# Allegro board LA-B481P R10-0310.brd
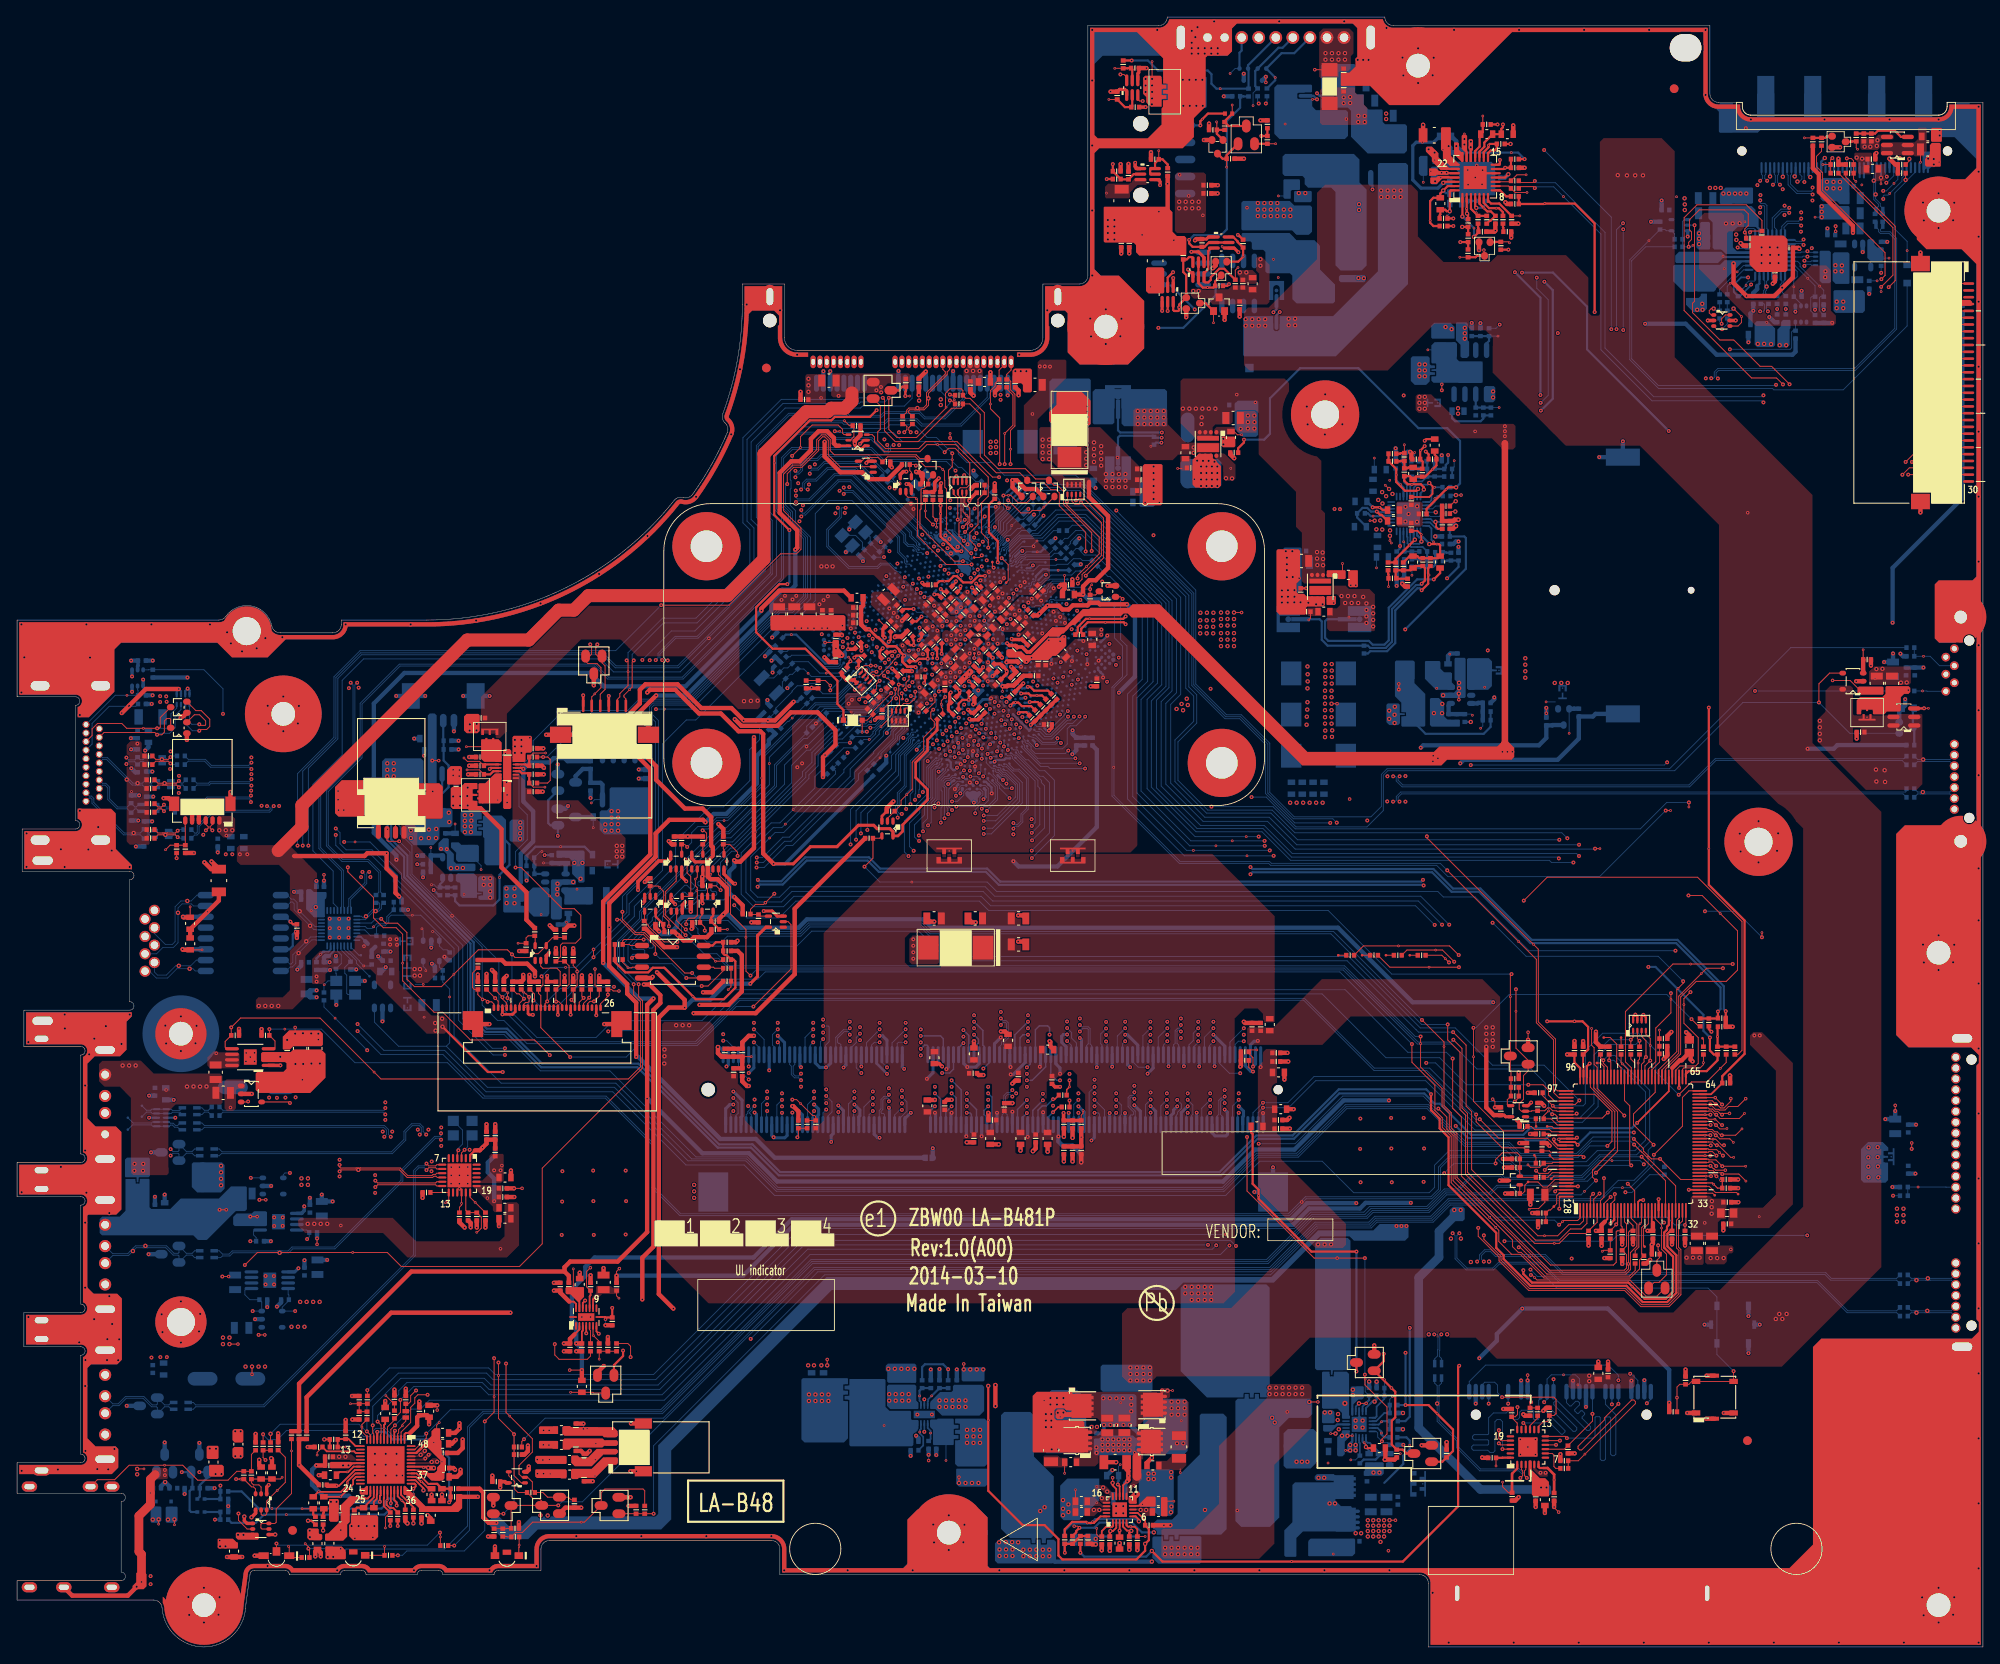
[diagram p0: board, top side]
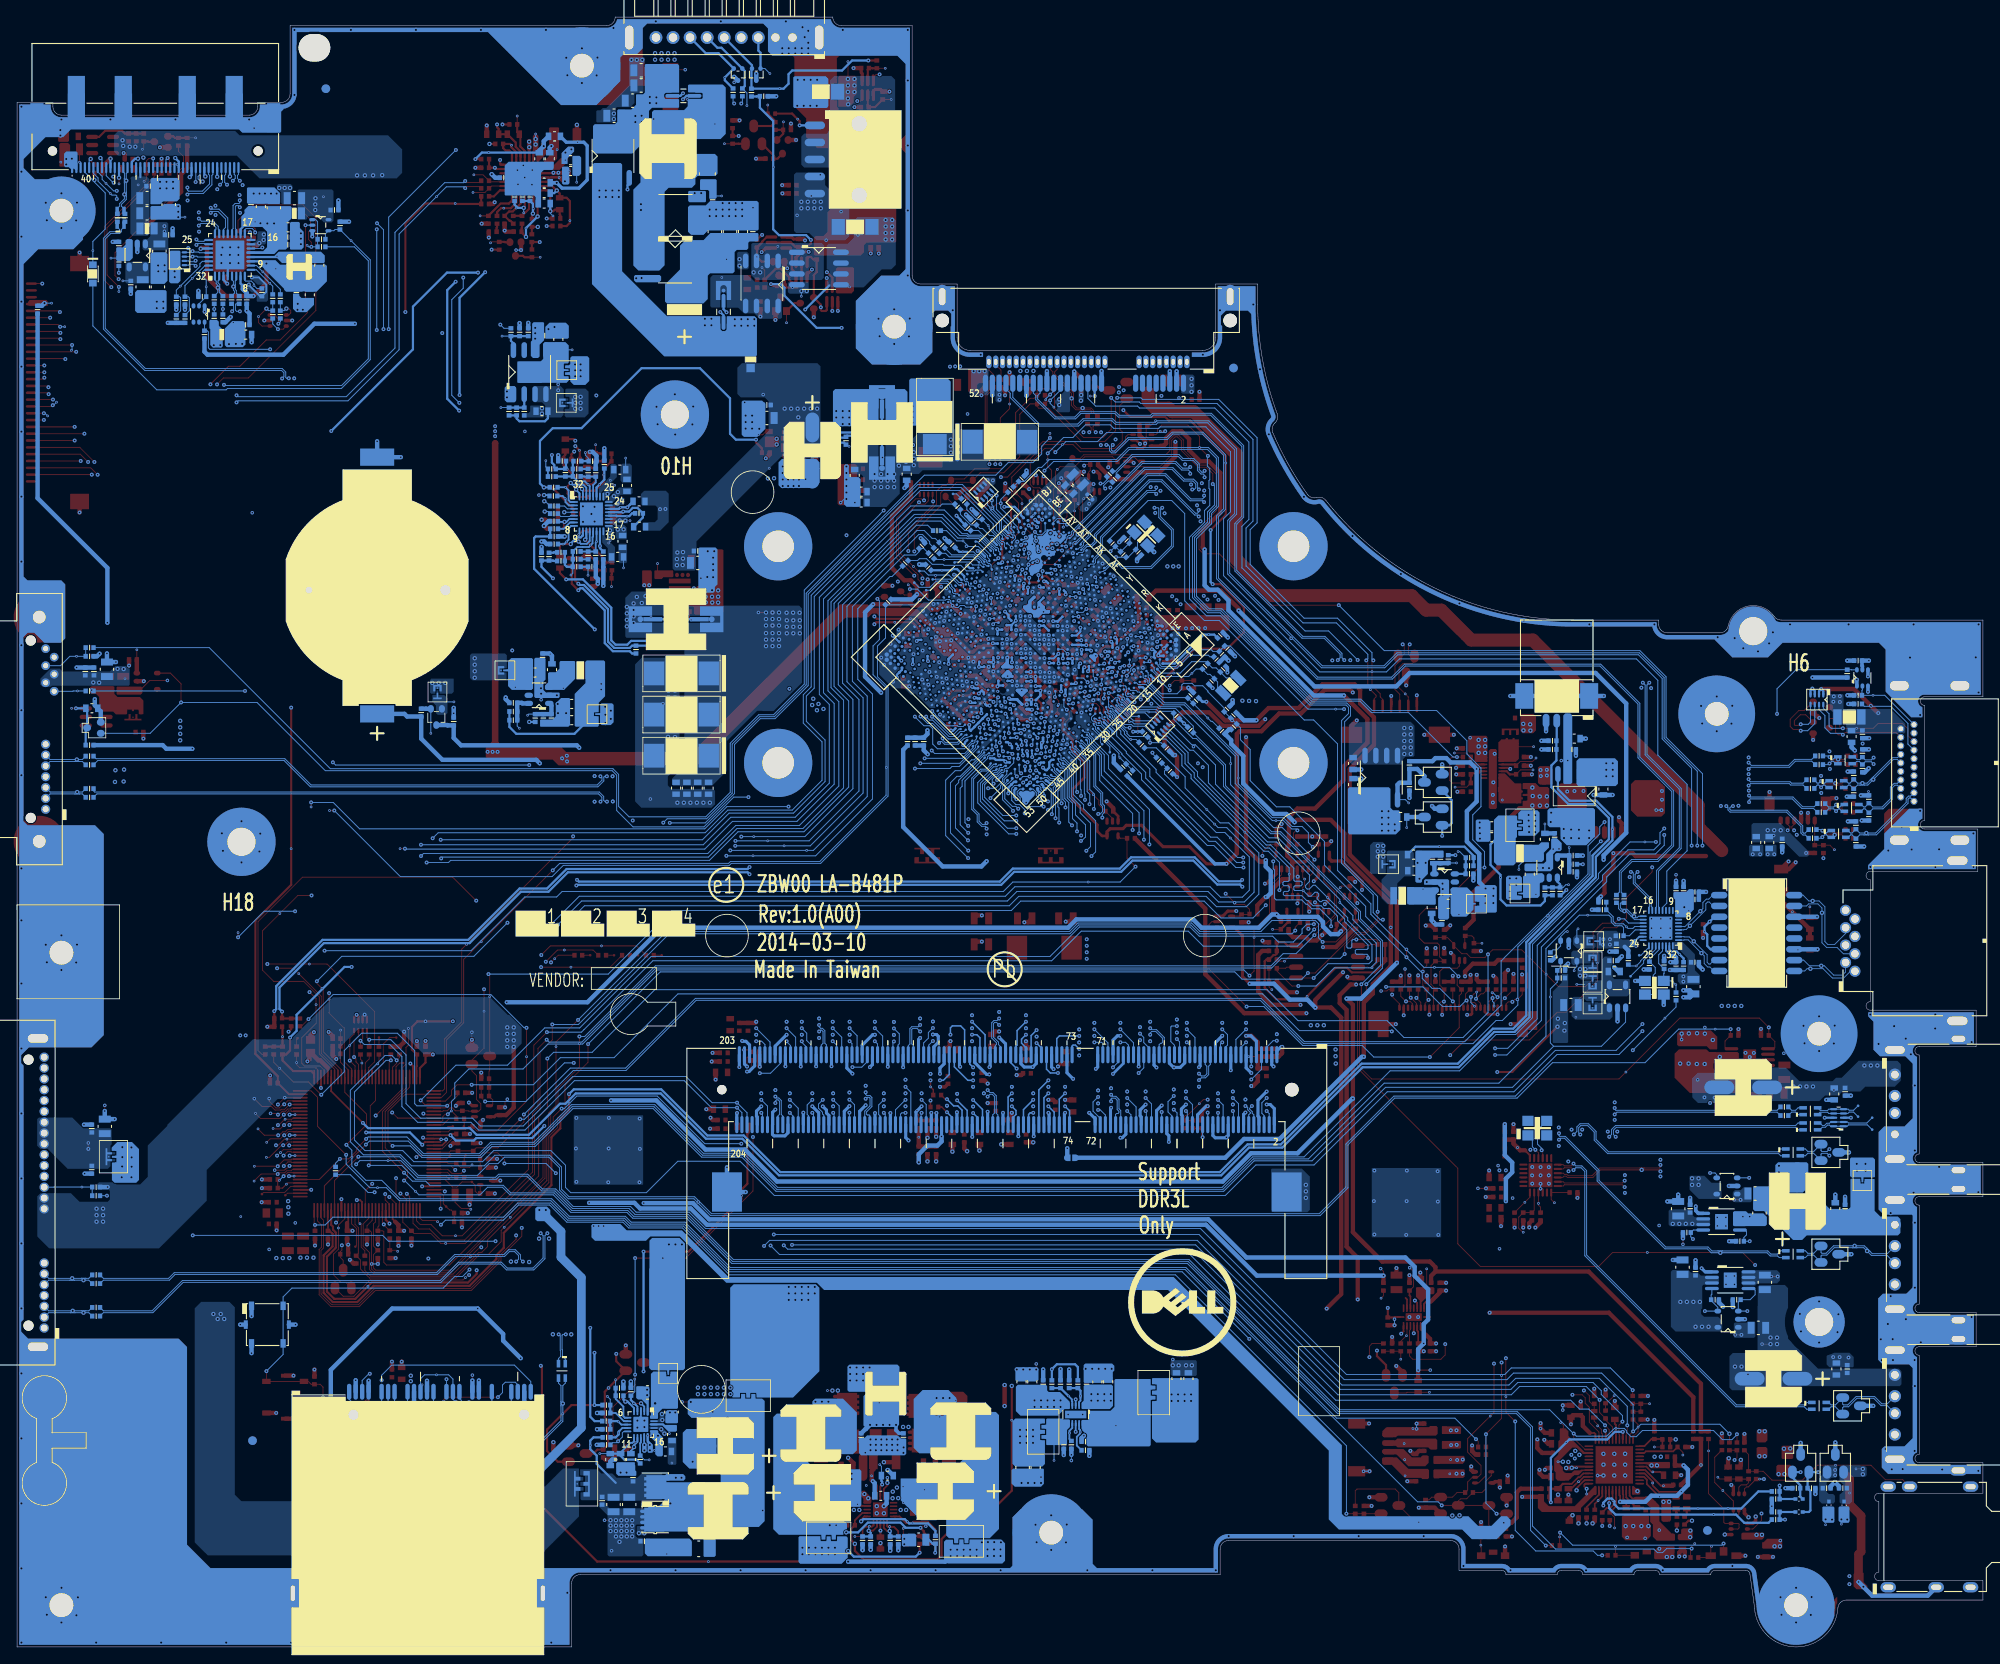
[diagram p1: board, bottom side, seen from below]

Outline 230.4 x 191.1 mm; copper layers: TOP, VCC, IN1, IN2, GND, BOTTOM. Coordinates in mm from the lower left corner of the outline.
Outline path: 0,120.4 0,111.4 6.85,111.4 arc(7.35,110.9) 6.85,110.4 6.85,96.9 arc(7.35,96.4) 6.85,95.9 0.6,95.9 0.6,90.94 13.2,90.94 arc(13.7,90.44) 13.2,89.94 13.2,75.66 arc(13.7,75.16) 13.2,74.66 0.8,74.66 0.8,70.4 7.47,70.4 arc(7.97,69.9) 7.47,69.4 7.47,57.8 arc(7.97,57.3) 7.47,56.8 0,56.8 0,52.8 7.47,52.8 arc(7.97,52.3) 7.47,51.8 7.47,40.2 arc(7.97,39.7) 7.47,39.2 0.8,39.2 0.8,35.2 7.47,35.2 arc(7.97,34.7) 7.47,34.2 7.47,22.6 arc(7.97,22.1) 7.47,21.6 0,21.6 0,18.02 12.2,18.02 arc(12.7,17.53) 12.2,17.02 12.2,8.78 arc(12.7,8.28) 12.2,7.78 0,7.78 0,5.5 16,5.5 arc(16.68,5.23) 17,4.57 arc(21.88,0) 26.77,4.55 arc(26.8,4.88) 26.84,5.22 27.3,8.48 arc(27.45,8.83) 27.8,8.98 31.4,8.98 arc(31.75,8.83) 31.9,8.48 37.9,8.48 arc(38.05,8.83) 38.4,8.98 40.4,8.98 arc(40.75,8.83) 40.9,8.48 46.9,8.48 arc(47.05,8.83) 47.4,8.98 49.4,8.98 arc(49.75,8.83) 49.9,8.48 55.9,8.48 arc(56.05,8.83) 56.4,8.98 61.4,8.98 61.4,11.48 arc(61.69,12.19) 62.4,12.48 88.4,12.48 arc(89.11,12.19) 89.4,11.48 89.4,8.48 164.4,8.48 arc(165.11,8.19) 165.4,7.48 165.4,0 230.4,0 230.4,181.1 226.2,181.1 226.2,180.6 arc(225.91,179.89) 225.2,179.6 203.2,179.6 arc(202.49,179.89) 202.2,180.6 202.2,181.1 199.4,181.1 arc(198.69,181.39) 198.4,182.1 198.4,190.1 161.3,190.1 arc(160.59,190.39) 160.3,191.1 134.8,191.1 arc(134.51,190.39) 133.8,190.1 125.5,190.1 125.5,160.8 arc(125.21,160.09) 124.5,159.8 120.23,159.8 120.23,153.52 arc(119.79,152.46) 118.73,152.02 91.43,152.02 arc(90.37,152.46) 89.93,153.52 89.93,159.8 85,159.8 85,157.4 arc(84.42,150.9) 82.71,144.59 arc(82.68,144.01) 82.98,143.51 arc(83.29,142.98) 83.23,142.37 arc(81.4,138.65) 79.17,135.14 arc(78.68,134.78) 78.07,134.77 arc(77.49,134.76) 77.01,134.43 arc(64.11,124.09) 48,120.4 38,120.4 38,119.9 arc(37.71,119.19) 37,118.9 30.84,118.9 arc(30.21,119.13) 29.86,119.7 arc(27.53,122.04) 24.46,120.83 arc(24.11,120.51) 23.65,120.4 0,120.4

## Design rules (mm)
net group CARD-READER: nets MS_INS# SD_CD#
net group CLK_PCIE_LAN: nets CLK_PCIE_LAN CLK_PCIE_LAN#
net group CLK_PCIE_WLAN: nets CLK_PCIE_WLAN CLK_PCIE_WLAN#
net group CPU_EDP_0_C: nets CPU_EDP_N0_C CPU_EDP_P0_C
net group CPU_EDP_AUX_C: nets CPU_EDP_AUX#_C CPU_EDP_AUX_C
net group DDI0_RCOMP: nets DDI0_RCOMPN DDI0_RCOMPP
net group DDR_A_ODT0: nets DDR_A_ODT0 M_ODT0
net group DDR_A_ODT2: nets DDR_A_ODT2 M_ODT1
net group DIFFPAIR1: nets CSCL CSDA
net group DIFFPAIR2: nets CSIN CSIP
net group DIFFPAIR3: nets DBG_UART_RXD DBG_UART_TXD
net group EDP_CPU_AUX: nets EDP_CPU_AUX EDP_CPU_AUX#
net group EDP_CPU_LANE_0: nets EDP_CPU_LANE_N0 EDP_CPU_LANE_P0
net group HDMI_CLK: nets HDMI_CLK+ HDMI_CLK-
net group HDMI_TX0: nets HDMI_TX0+ HDMI_TX0-
net group HDMI_TX1: nets HDMI_TX1+ HDMI_TX1-
net group HDMI_TX2: nets HDMI_TX2+ HDMI_TX2-
net group ICLK_USB_TERM: nets ICLK_USB_TERMN ICLK_USB_TERMP
net group LVDS_A0: nets LVDS_A0+ LVDS_A0-
net group LVDS_A1: nets LVDS_A1+ LVDS_A1-
net group LVDS_A2: nets LVDS_A2+ LVDS_A2-
net group LVDS_ACLK: nets LVDS_ACLK+ LVDS_ACLK-
net group MDI0: nets MDI0+ MDI0-
net group MDI1: nets MDI1+ MDI1-
net group MDO0: nets MDO0+ MDO0-
net group MDO1: nets MDO1+ MDO1-
net group MS_CLK_SD_WP: nets MS_CLK_SD_WP MS_CLK_SD_WP_R
net group MS_D2_SD_CLK: nets MS_D2_SD_CLK MS_D2_SD_CLK_R
net group PCH_USB3_RX0_: nets PCH_USB3_RX0_N PCH_USB3_RX0_P
net group PCH_USB3_TX0_: nets PCH_USB3_TX0_N PCH_USB3_TX0_P
net group PCH_USB3_TX0__C: nets PCH_USB3_TX0_N_C PCH_USB3_TX0_P_C
net group PCIE_PRX_C_DTX_0: nets PCIE_PRX_C_DTX_N0 PCIE_PRX_C_DTX_P0
net group PCIE_PRX_DTX_1: nets PCIE_PRX_DTX_N1 PCIE_PRX_DTX_P1
net group PCIE_PTX_C_DRX_0: nets PCIE_PTX_C_DRX_N0 PCIE_PTX_C_DRX_P0
net group PCIE_PTX_C_DRX_1: nets PCIE_PTX_C_DRX_N1 PCIE_PTX_C_DRX_P1
net group PCIE_PTX_DRX_0: nets PCIE_PTX_DRX_N0 PCIE_PTX_DRX_P0
net group PCIE_PTX_DRX_1: nets PCIE_PTX_DRX_N1 PCIE_PTX_DRX_P1
net group PCIE_RCOMP: nets PCIE_RCOMPN PCIE_RCOMPP
net group SATA_PRX_DTX_0: nets SATA_PRX_DTX_N0 SATA_PRX_DTX_P0
net group SATA_PRX_DTX_0_C: nets SATA_PRX_DTX_N0_C SATA_PRX_DTX_P0_C
net group SATA_PRX_DTX_1: nets SATA_PRX_DTX_N1 SATA_PRX_DTX_P1
net group SATA_PRX_DTX_1_C: nets SATA_PRX_DTX_N1_C SATA_PRX_DTX_P1_C
net group SATA_PTX_DRX_0: nets SATA_PTX_DRX_N0 SATA_PTX_DRX_P0
net group SATA_PTX_DRX_0_C: nets SATA_PTX_DRX_N0_C SATA_PTX_DRX_P0_C
net group SATA_PTX_DRX_1: nets SATA_PTX_DRX_N1 SATA_PTX_DRX_P1
net group SATA_PTX_DRX_1_C: nets SATA_PTX_DRX_N1_C SATA_PTX_DRX_P1_C
net group SATA_RCOMP: nets SATA_RCOMPN SATA_RCOMPP
net group TMDS_L_TX0: nets TMDS_L_TX0N TMDS_L_TX0P
net group TMDS_L_TX1: nets TMDS_L_TX1N TMDS_L_TX1P
net group TMDS_L_TX2: nets TMDS_L_TX2N TMDS_L_TX2P
net group TMDS_L_TXC: nets TMDS_L_TXCN TMDS_L_TXCP
net group TMDS_TX0: nets TMDS_TX0N TMDS_TX0P
net group TMDS_TX1: nets TMDS_TX1N TMDS_TX1P
net group TMDS_TX2: nets TMDS_TX2N TMDS_TX2P
net group TMDS_TXC: nets TMDS_TXCN TMDS_TXCP
net group USB3R2_JUSB1_R: nets USB3RN2_JUSB1_R USB3RP2_JUSB1_R
net group USB3T2_JUSB1_R: nets USB3TN2_JUSB1_R USB3TP2_JUSB1_R
net group USB20_0: nets USB20_N0 USB20_P0
net group USB20_1: nets USB20_N1 USB20_P1
net group USB20_2: nets USB20_N2 USB20_P2
net group USB20_CAM_7_R: nets USB20_CAM_N7_R USB20_CAM_P7_R
net group USB20_CPU_3: nets USB20_CPU_N3 USB20_CPU_P3
net group USB20_CR_3_R: nets USB20_CR_N3_R USB20_CR_P3_R
net group USB20_HUB_1: nets USB20_HUB_N1 USB20_HUB_P1
net group USB20_HUB_2: nets USB20_HUB_N2 USB20_HUB_P2
net group USB20_HUB_3: nets USB20_HUB_N3 USB20_HUB_P3
net group USB20_JUSB1_0_R: nets USB20_JUSB1_N0_R USB20_JUSB1_P0_R
net group USB20_JUSB2_1_R: nets USB20_JUSB2_N1_R USB20_JUSB2_P1_R
net group USB20_JUSB3_3_R: nets USB20_JUSB3_N3_R USB20_JUSB3_P3_R
net group VCORE_VSNS: nets VCORE_GSNS VCORE_VSNS
net group VSUM: nets N100765116 VSUM-
net group VSUMG: nets N100764996 VSUMG-
net group 10: nets AUD_HP_OUT_L_CN AUD_HP_OUT_R_CN HPOUT-L HPOUT-R LINE-IN-L LINE-IN-R MIC_IN
net group 15: nets CLK_SMB EC_SPI_CLK_R LAN_CLKREQ# MIC_CLK MIC_CLK_C PMC_SUSCLK SOC_I2C0_CLK
net group 20: nets DDR_RCOMP0 DDR_RCOMP1 DDR_RCOMP2 DDR_TERMN0 DDR_TERMN1 GPIO_RCOMP HDA_BIT_CLK HDA_BITCLK_AUDIO HDA_RCOMP HDA_RST# HDA_RST_AUDIO# HSIC_RCOMP HUB_XIN HUB_XOUT ICLK_ICOMP ICLK_RCOMP LPC_RCOMP USB3_REXT0 USB_RCOMP VGFX_VSNS VSUM+ VSUMG+ XTAL_25M_IN XTAL_25M_OUT XTLI XTLO
net group AUDIO-SPK: nets SPK_L1-_CONN SPK_L2+_CONN SPK_R1-_CONN SPK_R2+_CONN
net group HDA: nets HDA_SDIN0 HDA_SDOUT HDA_SDOUT_AUDIO HDA_SYNC HDA_SYNC_AUDIO
net group HDMI: nets CPU_DPB_CTRLCLK_R CPU_DPB_CTRLDAT_R HDMI_DDCCLK HDMI_DDCDATA
net group KB: nets KSI0 KSI1 KSI2 KSI3 KSI4 KSI5 KSI6 KSI7 KSO0 KSO1 KSO2 KSO3 KSO4 KSO5 KSO6 KSO7 KSO8 KSO9 KSO10 KSO11 KSO12 KSO13 KSO14 KSO15 KSO16
net group LPC: nets LPC_AD0 LPC_AD1 LPC_AD2 LPC_AD3 LPC_CLK_0 LPC_CLK_1 LPC_CLK_EC LPC_FRAME# SOC_SERIRQ
net group RTC: nets ILB_RTC_EXTPAD ILB_RTC_X1 ILB_RTC_X2 RTC_RST# RTC_TEST#
net group SMBUS: nets EC_RX EC_SMB_CK1 EC_SMB_CK2 EC_SMB_DA1 EC_SMB_DA2 EC_TX PCU_SMB_CLK PCU_SMB_DATA TP_CLK TP_DATA
net group SPI: nets SOC_SPI_CLK SOC_SPI_CS0# SOC_SPI_MISO SOC_SPI_MOSI SPI_CLK SPI_CS0# SPI_HOLD# SPI_MISO SPI_MOSI SPI_WP#
net group SVID: nets VR_SVID_ALERT# VR_SVID_CLK VR_SVID_CLK_R VR_SVID_DATA VR_SVID_DATA_R
net group XDP: nets XDP_H_PRDY# XDP_H_PREQ_BUF# XDP_H_TCK XDP_H_TDI XDP_H_TDO XDP_H_TMS XDP_H_TRST#
nets with their own width: min track width 0.254; nets +BIOS_SPI MIC_IN_R RING2 XTLI_R
nets with their own width: min track width 0.508; nets +0.675VSP +1.0VALW +1.0VALWP +1.0VS +1.0VS_R +1.05VS +1.5VS +1.05VS_SOC +1.05VSP +1.5VSP +1.8VALW +1.8VALWP +1.8VGS +1.8VS +1.8VS_OUT +1.8VSP_ON +1.35V +1.35V_SOC +1.35VP +1.35VS +1.35VS_OUT +3V_HUB +3V_WLAN +3VALW +3VALW_EC +3VALW_SOC +3VALWP +3VLP +3VS +3VS_CAM +3VS_LCDIN +3VS_OUT +3VS_RT +3VS_SOC +5VALW +5VALWP +5VS +5VS_TOUCH +AVCC33 +CHGRTC +CODEC_AVDD2 +DDR_SOC_VREF +DIMM1_VREF_CA +DIMM1_VREF_DQ +DVCC33 +EC_VCCA +INV_PWR_SRC +INV_PWR_SRC_R +MIC2-VREFO +RTCBATT +RTCBATT_R +RTCVCC +SOC_VCC +SOC_VNN +SW_LX +SWR_V12 +V18R +VDISPLAY_VCC GND
nets with their own width: min track width 0.762; nets +FAN_POWER INT-SPK-L+ INT-SPK-L- INT-SPK-R+ INT-SPK-R-
nets with their own width: min track width 1.016; nets +5V_HUB +5V_PVDD +5VA +LAN_VDD +VCC_3IN1
nets with their own width: min track width 1.524; nets +0.675VS +LAN_IO +LCDVDD +LCDVDD_CONN TL_ENVDD
nets with their own width: min track width 2.032; nets +5V_USB_PWR1 +5V_USB_PWR2 +5V_USB_PWR3
nets with their own width: min track width 4.572; nets +5VS_OUT

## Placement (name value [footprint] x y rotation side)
C182  0.1U_0402_16V7K  [C_0402]  77 95.02 270 top
C967  330P_0402_50V7K  [C_0402]  106.84 23.24 90 bottom
C976  330P_0402_50V7K  [C_0402]  104.73 23.06 0 bottom
C979  .1U_0402_16V7K  [C_0402]  108.11 31.27 270 bottom
C980  .1U_0402_16V7K  [C_0402]  107.09 30.35 90 bottom
C1034  1U_0402_6.3V6K  [C_0402]  95.94 118.68 270 top
C1035  1U_0402_6.3V6K  [C_0402]  95.94 115.48 90 top
C1036  1U_0402_6.3V6K  [C_0402]  106 117.49 315 top
C1037  1U_0402_6.3V6K  [C_0402]  105.25 116.22 225 top
C1038  0.47U_0402_6.3V6K  [C_0402]  110.08 111.4 225 top
C1039  0.01U_0402_16V7K  [C_0402]  104.33 119.11 315 top
C1040  1U_0402_6.3V6K  [C_0402]  112.06 112.64 45 top
C1041  1U_0402_6.3V6K  [C_0402]  113.88 116.39 135 top
C1042  1U_0402_6.3V6K  [C_0402]  115.01 116.5 135 top
C1043  1U_0402_6.3V6K  [C_0402]  109.43 122.98 315 top
C1044  1U_0402_6.3V6K  [C_0402]  106.65 119.4 225 top
C1045  1U_0402_6.3V6K  [C_0402]  103.86 114.44 225 top
C1046  1U_0402_6.3V6K  [C_0402]  116.56 121.8 135 top
C1047  1U_0402_6.3V6K  [C_0402]  115.92 121.16 135 top
C1048  1U_0402_6.3V6K  [C_0402]  95.41 121.56 270 top
C1049  1U_0402_6.3V6K  [C_0402]  94.39 121.56 270 top
C1050  1U_0402_6.3V6K  [C_0402]  113.62 123.59 315 top
C1051  1U_0402_6.3V6K  [C_0402]  117.82 118.11 45 top
C1052  1U_0402_6.3V6K  [C_0402]  110.81 123.13 315 top
C1053  1U_0402_6.3V6K  [C_0402]  118.45 117.48 45 top
C1054  1U_0402_6.3V6K  [C_0402]  112.77 110.16 315 top
C1055  1U_0402_6.3V6K  [C_0402]  112.13 109.52 315 top
C1056  22U_0805_6.3V6M  [C_0805]  92.87 121.96 270 top
C1057  22U_0805_6.3V6M  [C_0805]  91.09 121.96 270 top
C1058  1U_0402_6.3V6K  [C_0402]  117.19 117.24 225 top
C1059  22U_0805_6.3V6M  [C_0805]  89.31 121.96 270 top
C1060  1U_0402_6.3V6K  [C_0402]  101.31 115.96 45 top
C1061  1U_0402_6.3V6K  [C_0402]  115.52 114.98 225 top
C1062  1U_0402_6.3V6K  [C_0402]  107.08 117.7 315 top
C1063  .1U_0402_16V7K  [C_0402]  98.91 120.09 180 top
C1064  1U_0402_6.3V6K  [C_0402]  118.15 120.05 225 top
C1065  1U_0402_6.3V6K  [C_0402]  98.91 121.87 180 top
C1066  1U_0402_6.3V6K  [C_0402]  117.43 120.59 225 top
C1067  1U_0402_6.3V6K  [C_0402]  98.91 120.98 180 top
C1068  1U_0402_6.3V6K  [C_0402]  108.8 122.34 315 top
C1069  .1U_0402_16V7K  [C_0402]  114.26 124.48 315 top
C1070  0.01U_0402_16V7K  [C_0402]  117.94 116.11 225 top
C1071  1U_0402_6.3V6K  [C_0402]  119.61 123.19 135 top
C1072  1U_0402_6.3V6K  [C_0402]  120.24 123.83 135 top
C1073  1U_0402_6.3V6K  [C_0402]  122.76 124.53 0 top
C1074  1U_0402_6.3V6K  [C_0402]  104.34 117.83 135 top
C1076  .1U_0402_16V7K  [C_0402]  84.99 69.21 90 top
C1078  .1U_0402_16V7K  [C_0402]  122.69 58.68 270 top
C1117  .1U_0402_16V7K  [C_0402]  56.47 52.75 0 top
C1118  .1U_0402_16V7K  [C_0402]  56.47 53.77 0 top
C1119  10U_0603_10V6M  [C_0603]  56.48 55.04 0 top
C1120  10U_0603_6.3V6M  [C_0603]  57.88 50.21 180 top
C1121  0.01U_0402_16V7K  [C_0402]  55.02 59.48 90 top
C1122  0.01U_0402_16V7K  [C_0402]  52.86 50.01 90 top
C1123  330P_0402_50V7K  [C_0402]  53.8 102.31 0 top
C1124  .1U_0402_16V7K  [C_0402]  57.51 100.53 180 top
C1125  .1U_0402_16V7K  [C_0402]  60.94 102.31 180 top
C1126  .1U_0402_16V7K  [C_0402]  53.8 104.34 0 top
C1127  330P_0402_50V7K  [C_0402]  53.8 103.33 0 top
C1128  .1U_0402_16V7K  [C_0402]  60.94 103.33 180 top
C1129  4.7U_0603_6.3V6K  [C_0603]  73.82 102.88 90 bottom
C1130  4.7U_0603_6.3V6K  [C_0603]  73.82 101.81 270 bottom
C1131  .1U_0402_16V7K  [C_0402]  67.21 101.32 270 bottom
C1138  .1U_0402_16V7K  [C_0402]  105.64 24.08 180 bottom
C1139  .1U_0402_16V7K  [C_0402]  107.72 23.24 90 bottom
C1143  1U_0402_6.3V6K  [C_0402]  105.06 31.27 270 bottom
C1144  1U_0402_6.3V6K  [C_0402]  110.14 31.27 270 bottom
C1145  1U_0402_6.3V6K  [C_0402]  60.94 100.28 180 top
C1146  1U_0402_6.3V6K  [C_0402]  60.94 105.36 180 top
C1147  1U_0402_6.3V6K  [C_0402]  51.46 100.45 90 top
C1148  1U_0402_6.3V6K  [C_0402]  54.84 108.91 180 top
C2305  10U_0603_6.3V6M  [C_0603]  112.68 30.36 90 bottom
C2306  10U_0603_6.3V6M  [C_0603]  111.41 30.36 90 bottom
C2307  10U_0805_10V4Z  [C_0805]  112.55 21.88 270 bottom
C2308  10U_0603_6.3V6M  [C_0603]  111.03 21.73 270 bottom
C2316  10U_0603_6.3V6M  [C_0603]  102.52 30.36 90 bottom
C2318  10U_0603_6.3V6M  [C_0603]  103.79 30.36 90 bottom
C2323  10U_0603_6.3V6M  [C_0603]  94.52 30.74 90 bottom
C2324  10U_0603_6.3V6M  [C_0603]  93.12 30.74 90 bottom
CA1  10U_0603_6.3V6M  [C_0603]  28.6 19.7 90 top
CA2  10U_0603_6.3V6M  [C_0603]  29.87 19.7 90 top
CA21  22P_0402_50V8J  [C_0402]  44.22 28.57 90 top
CA22  22P_0402_50V8J  [C_0402]  45.56 28.51 90 top
CA23  2.2U_0603_6.3V6K  [C_0603]  41.81 14.93 90 top
CA24  1U_0402_6.3V6K  [C_0402]  46.45 15.17 90 top
CA25  1U_0402_6.3V6K  [C_0402]  45.49 15.17 90 top
CA29  1000P_0402_50V7K  [C_0402]  65.5 25.27 90 top
CA30  1000P_0402_50V7K  [C_0402]  65.5 23.9 270 top
CA31  1000P_0402_50V7K  [C_0402]  66.45 21.71 90 top
CA32  1000P_0402_50V7K  [C_0402]  66.45 20.34 270 top
CA33  100P_0402_50V8J  [C_0402]  21.42 18.62 0 bottom
CA38  100P_0402_50V8J  [C_0402]  15.95 18.62 0 bottom
CA39  100P_0402_50V8J  [C_0402]  20.55 18.62 180 bottom
CA40  100P_0402_50V8J  [C_0402]  18.77 18.62 180 bottom
CA51  0.1U_0402_16V7K  [C_0402]  38.33 16.33 180 top
CA53  4.7U_0603_6.3V6K  [C_0603]  49.18 23.82 0 top
CA54  0.1U_0402_16V7K  [C_0402]  49.48 22.74 0 top
CA55  4.7U_0603_6.3V6K  [C_0603]  49.24 19.95 0 top
CA56  0.1U_0402_16V7K  [C_0402]  49.74 20.98 0 top
CA57  4.7U_0603_6.3V6K  [C_0603]  48.48 16.14 270 top
CA58  0.1U_0402_16V7K  [C_0402]  47.4 16.09 270 top
CA59  4.7U_0603_6.3V6K  [C_0603]  48.29 26.93 90 top
CA60  0.1U_0402_16V7K  [C_0402]  47.15 27.18 90 top
CA61  4.7U_0603_6.3V6K  [C_0603]  49.8 18.55 270 top
CA62  10U_0603_6.3V6M  [C_0603]  40.61 14.93 90 top
CA63  10U_0603_6.3V6M  [C_0603]  48.58 17.16 90 top
CA64  10U_0603_6.3V6M  [C_0603]  43.15 28.08 270 top
CA65  0.1U_0402_16V7K  [C_0402]  41.01 26.67 90 top
CA67  4.7U_0603_6.3V6K  [C_0603]  35.96 17.6 270 top
CA68  4.7U_0603_6.3V6K  [C_0603]  34.71 17.6 270 top
CA69  100P_0402_50V8J  [C_0402]  40.1 28.51 90 top
CA71  4.7U_0603_6.3V6K  [C_0603]  38.57 15.19 180 top
CA74  10U_0603_6.3V6M  [C_0603]  37.43 20.14 180 top
CC1  .1U_0402_16V7K  [C_0402]  116.29 111.33 45 top
CC2  .1U_0402_16V7K  [C_0402]  124.14 106.61 270 bottom
CC3  0.1U_0402_10V7K  [C_0402]  102.66 137.22 135 bottom
CC4  0.1U_0402_10V7K  [C_0402]  102.03 136.58 135 bottom
CC5  0.1U_0402_10V7K  [C_0402]  104.93 143.38 90 top
CC6  0.1U_0402_10V7K  [C_0402]  103.79 143.38 90 top
CC7  22P_0402_50V8J  [C_0402]  124.69 128.78 135 bottom
CC8  10P_0402_50V8J  [C_0402]  98.52 107.33 225 bottom
CC9  10P_0402_25V8K  [C_0402]  100.04 129.42 45 bottom
CC10  10P_0402_25V8K  [C_0402]  99.29 128.67 225 bottom
CC11  .1U_0402_16V7K  [C_0402]  63.15 83.18 90 top
CC12  .1U_0402_16V7K  [C_0402]  113 136.66 135 bottom
CC13  .1U_0402_16V7K  [C_0402]  101.37 109.88 270 top
CC14  .1U_0402_16V7K  [C_0402]  93.88 113.31 270 top
CC15  .1U_0402_16V7K  [C_0402]  90.14 116.09 225 bottom
CC16  .1U_0402_16V7K  [C_0402]  89.51 116.73 225 bottom
CC17  15P_0402_50V8J  [C_0402]  89.38 114.3 135 bottom
CC18  15P_0402_50V8J  [C_0402]  90.08 113.53 315 bottom
CC19  .1U_0402_16V7K  [C_0402]  86.9 85.88 270 top
CC20  1U_0402_6.3V6K  [C_0402]  88.28 110.3 315 bottom
CC21  .1U_0402_16V7K  [C_0402]  82.76 82.62 0 top
CC22  1U_0402_6.3V6K  [C_0402]  93.19 111.26 135 bottom
CC23  .1U_0402_16V7K  [C_0402]  179.23 108.05 90 bottom
CC24  10P_0402_50V8J  [C_0402]  82.76 78.05 0 top
CC25  10P_0402_50V8J  [C_0402]  117.97 131.55 45 bottom
CC26  10P_0402_50V8J  [C_0402]  117.31 132.21 45 bottom
CC27  1U_0402_6.3V6K  [C_0402]  117.09 113.02 135 top
CC28  .1U_0402_16V7K  [C_0402]  117.73 113.65 135 top
CC29  2.2U_0402_6.3V6M  [C_0402]  121.26 108.15 180 top
CC30  2.2U_0402_6.3V6M  [C_0402]  119.66 116.03 270 top
CC31  2.2U_0402_6.3V6M  [C_0402]  126.55 112.63 90 top
CC32  2.2U_0402_6.3V6M  [C_0402]  120.55 116.03 270 top
CC33  10U_0603_6.3V6M  [C_0603]  126.01 117.42 90 top
CC34  10U_0603_6.3V6M  [C_0603]  122.95 116.04 135 top
CC35  10U_0603_6.3V6M  [C_0603]  106.6 135.22 45 bottom
CC36  22U_0805_6.3V6M  [C_0805]  105.47 136.25 45 bottom
CC38  22U_0805_6.3V6M  [C_0805]  102.74 123.99 225 top
CC39  1U_0402_6.3V6K  [C_0402]  110.35 109.96 225 top
CC40  1U_0402_6.3V6K  [C_0402]  108.39 117.66 135 top
CC41  1U_0402_6.3V6K  [C_0402]  111.55 111.94 315 top
CC42  1U_0402_6.3V6K  [C_0402]  113.88 114.61 45 top
CC43  1U_0402_6.3V6K  [C_0402]  114.64 112.78 45 top
CC44  1U_0402_6.3V6K  [C_0402]  113.44 113.76 135 top
CC45  1U_0402_6.3V6K  [C_0402]  107.53 121.04 45 top
CC46  1U_0402_6.3V6K  [C_0402]  106.51 122.18 45 top
CC47  1U_0402_6.3V6K  [C_0402]  108.16 120.4 45 top
CC49  .1U_0402_16V7K  [C_0402]  64.16 77.09 90 top
CC50  .1U_0402_16V7K  [C_0402]  54 77.09 90 top
CC51  .1U_0402_16V7K  [C_0402]  63.15 77.09 90 top
CC52  .1U_0402_16V7K  [C_0402]  55.02 77.09 90 top
CC53  .1U_0402_16V7K  [C_0402]  64.16 80.39 90 top
CC54  .1U_0402_16V7K  [C_0402]  60.1 77.09 90 top
CC55  .1U_0402_16V7K  [C_0402]  56.04 77.09 90 top
CC56  .1U_0402_16V7K  [C_0402]  65.18 77.09 90 top
CC57  .1U_0402_16V7K  [C_0402]  61.12 77.09 90 top
CC58  .1U_0402_16V7K  [C_0402]  57.05 77.09 90 top
CC59  .1U_0402_16V7K  [C_0402]  66.2 77.09 90 top
CC60  .1U_0402_16V7K  [C_0402]  58.07 77.09 90 top
CC61  .1U_0402_16V7K  [C_0402]  67.21 77.09 90 top
CC62  .1U_0402_16V7K  [C_0402]  59.08 77.09 90 top
CC63  .1U_0402_16V7K  [C_0402]  68.23 77.09 90 top
CC64  .1U_0402_16V7K  [C_0402]  62.13 77.09 90 top
CC65  .1U_0402_16V7K  [C_0402]  69.24 77.09 90 top
CD1  2.2U_0402_6.3V6M  [C_0402]  83.98 69.21 90 top
CD2  0.1U_0402_10V7K  [C_0402]  82.96 69.21 90 top
CD3  0.1U_0402_10V7K  [C_0402]  91.57 60.82 90 top
CD4  1U_0402_6.3V6K  [C_0402]  112.14 60.08 270 top
CD5  1U_0402_6.3V6K  [C_0402]  115.7 62.85 90 top
CD6  1U_0402_6.3V6K  [C_0402]  108.72 62.98 90 top
CD7  1U_0402_6.3V6K  [C_0402]  114.76 61.78 180 top
CD8  1U_0402_6.3V6K  [C_0402]  119.38 60.08 270 top
CD9  1U_0402_6.3V6K  [C_0402]  111.59 67.26 0 top
CD10  1U_0402_6.3V6K  [C_0402]  121.29 66.94 270 top
CD11  1U_0402_6.3V6K  [C_0402]  117.35 67.32 270 top
CD12  10U_0603_6.3V6M  [C_0603]  114.05 60.32 270 top
CD13  10U_0603_6.3V6M  [C_0603]  112.14 68.83 90 top
CD14  10U_0603_6.3V6M  [C_0603]  106.68 62.73 90 top
CD15  330U_D2_2.5V_R6M  [C_D2]  113.21 81.99 180 top
CD16  10U_0603_6.3V6M  [C_0603]  120.78 60.32 270 top
CD17  10U_0603_6.3V6M  [C_0603]  107.51 69.8 270 top
CD18  10U_0603_6.3V6M  [C_0603]  117.61 60.32 270 top
CD19  10U_0603_6.3V6M  [C_0603]  116.15 70.42 90 top
CD20  10U_0603_6.3V6M  [C_0603]  120.08 70.04 0 top
CD21  2.2U_0402_6.3V6M  [C_0402]  122.69 61.73 270 top
CD22  0.1U_0402_10V7K  [C_0402]  123.7 61.73 270 top
CD24  0.1U_0402_10V7K  [C_0402]  147.12 69.66 0 top
CD25  0.1U_0402_10V7K  [C_0402]  147.12 68.64 0 top
CD26  0.1U_0402_10V7K  [C_0402]  147.37 60.77 0 top
CD27  0.1U_0402_10V7K  [C_0402]  147.37 61.78 0 top
CD28  10U_0603_6.3V6M  [C_0603]  147.13 67.37 0 top
CD29  10U_0603_6.3V6M  [C_0603]  147.39 63.05 0 top
CD30  2.2U_0402_6.3V6M  [C_0402]  144.73 72.25 90 top
CD31  0.1U_0402_10V7K  [C_0402]  145.75 72.25 90 top
CD32  330U_D2_2.5V_R6M  [C_D2]  149.33 104.49 0 bottom
CD62  22U_0603_6.3V6M  [C_0603]  146.82 72.26 90 top
CD63  0.1U_0402_10V7K  [C_0402]  56.62 19.38 180 top
CE1  0.1U_0402_10V7K  [C_0402]  199.98 52.14 0 top
CE2  0.1U_0402_10V7K  [C_0402]  191.72 48.79 270 top
CE5  1000P_0402_50V7K  [C_0402]  182.53 70.38 270 top
CE6  1000P_0402_50V7K  [C_0402]  185.7 47.88 90 top
CE7  0.1U_0402_10V7K  [C_0402]  200.89 49.6 180 top
CE8  0.1U_0402_10V7K  [C_0402]  192.48 69.54 0 top
CE9  100P_0402_50V8J  [C_0402]  200.77 66.11 180 top
CE11  0.1U_0402_10V7K  [C_0402]  199.85 53.8 0 top
CE12  0.1U_0402_10V7K  [C_0402]  186.72 46.51 270 top
CE15  0.1U_0402_10V7K  [C_0402]  173.89 62.35 90 top
CE16  4.7U_0805_10V4Z  [C_0805]  179.06 53.03 180 top
CE18  100P_0402_50V8J  [C_0402]  178.01 60.15 0 top
CE19  47P_0402_50V8J  [C_0402]  175.09 66.62 0 top
CE20  0.1U_0402_16V7K  [C_0402]  195.55 30.8 90 top
CE22  2.2U_0603_6.3V6K  [C_0603]  48.61 106.5 180 bottom
CE23  1000P_0402_50V7K  [C_0402]  48.62 105.23 180 bottom
CE24  0.01U_0402_16V7K  [C_0402]  49.99 106.25 0 bottom
CE25  2.2U_0603_6.3V6K  [C_0603]  44.48 101.29 270 bottom
CE26  0.1U_0402_10V7K  [C_0402]  183.54 69.47 90 top
CE27  0.1U_0402_10V7K  [C_0402]  184.18 48.79 270 top
CE28  0.1U_0402_10V7K  [C_0402]  188.12 46.51 270 top
CE29  220P_0402_50V8J  [C_0402]  193.96 48.79 270 top
CE30  0.1U_0402_10V7K  [C_0402]  178.72 58.16 90 top
CE31  0.1U_0402_10V7K  [C_0402]  88.87 117.36 225 bottom
CE33  0.1U_0402_10V7K  [C_0402]  179.18 50.87 180 top
CE34  0.1U_0402_10V7K  [C_0402]  176.13 56.21 180 top
CE35  220P_0402_50V8J  [C_0402]  176.13 53.16 180 top
CE36  0.047U_0402_16V4Z  [C_0402]  188.12 48.79 270 top
CG1  0.1U_0402_10V7K  [C_0402]  67.21 41.78 90 top
CG2  0.1U_0402_10V7K  [C_0402]  66.2 35.58 270 top
CG3  0.1U_0402_10V7K  [C_0402]  69.75 38.63 270 top
CG4  0.1U_0402_10V7K  [C_0402]  63.66 41.78 90 top
CG5  22U_0805_6.3V6M  [C_0805]  68.74 41.9 90 top
CG6  2.2U_0603_6.3V6K  [C_0603]  65.94 41.79 90 top
CG7  5P_0402_50V8C  [C_0402]  69.24 34.67 90 top
CG10  0.1U_0402_10V7K  [C_0402]  64.8 35.58 270 top
CI1  220U_6.3V_M  [C_MP6VLPS220MC4R2]  25.3 65.61 180 bottom
CI2  0.1U_0402_16V7K  [C_0402]  16.16 65.56 270 bottom
CI3  0.1U_0402_10V7K  [C_0402]  22.81 62.3 0 bottom
CI4  0.1U_0402_10V7K  [C_0402]  22.81 63.32 0 bottom
CI6  4.7U_0805_10V4Z  [C_0805]  35.72 50.53 90 bottom
CI7  0.1U_0402_16V7K  [C_0402]  34.32 50.92 90 bottom
CI8  220U_6.3V_M  [C_MP6VLPS220MC4R2]  21.75 49.47 270 bottom
CI9  0.1U_0402_16V7K  [C_0402]  16.16 50.92 90 bottom
CI10  0.1U_0402_16V7K  [C_0402]  33.68 43.56 90 bottom
CI11  4.7U_0805_10V4Z  [C_0805]  35.21 43.67 90 bottom
CI12  4.7U_0805_10V4Z  [C_0805]  33.18 69.33 90 top
CI13  0.1U_0402_16V7K  [C_0402]  29.57 71.7 180 top
CI14  0.1U_0402_16V7K  [C_0402]  31.65 69.47 90 top
CI15  0.1U_0402_16V7K  [C_0402]  25.1 71.7 0 top
CI17  0.1U_0402_16V7K  [C_0402]  28.02 47.57 0 bottom
CI18  47U_0805_6.3V4Z  [C_0805]  34.95 69.33 90 top
CI26  0.1U_0402_16V7K  [C_0402]  34.24 48.59 0 bottom
CI28  0.1U_0402_16V7K  [C_0402]  28.4 40.71 0 bottom
CI29  0.1U_0402_16V7K  [C_0402]  31.86 40.71 180 bottom
CI33  220U_6.3V_M  [C_MP6VLPS220MC4R2]  21.74 31.44 180 bottom
CI34  0.1U_0402_16V7K  [C_0402]  15.9 32.13 90 bottom
CI40  10U_0603_6.3V6M  [C_0603]  17.43 65.54 270 bottom
CI43  10U_0603_6.3V6M  [C_0603]  17.3 50.68 90 bottom
CI45  10U_0603_6.3V6M  [C_0603]  17.17 31.89 90 bottom
CL15  0.1U_0402_10V7K  [C_0402]  34.2 80.27 180 bottom
CL19  0.1U_0402_10V7K  [C_0402]  42.96 82.45 270 bottom
CL20  0.1U_0402_10V7K  [C_0402]  35.97 80.29 270 bottom
CL22  0.1U_0402_10V7K  [C_0402]  34.2 87.64 180 bottom
CL26  0.1U_0402_10V7K  [C_0402]  34.2 88.53 180 bottom
CL30  0.1U_0402_10V7K  [C_0402]  42.07 88.16 270 bottom
CL31  0.1U_0402_10V7K  [C_0402]  42.96 88.16 270 bottom
CL33  10P_1206_2KV8J  [C_1206]  23.65 88.53 90 top
CL34  0.1U_0402_10V7K  [C_0402]  35.97 88.2 90 bottom
CL35  1U_0402_6.3V6K  [C_0402]  35.08 88.2 90 bottom
CL36  10P_0402_50V8J  [C_0402]  37.37 80.41 270 bottom
CL37  10P_0402_50V8J  [C_0402]  39.08 79.44 90 bottom
CL38  0.1U_0603_25V7K  [C_0603]  43.91 79.2 180 bottom
CL39  1U_0402_6.3V6K  [C_0402]  43.78 80.46 180 bottom
CL41  0.01U_0402_16V7K  [C_0402]  32.79 83.82 90 top
CLRP1  SHORT PADS  [SHORTPADS]  106.84 57.35 0 bottom
CM40  0.047U_0402_16V4Z  [C_0402]  92.74 146.25 180 top
CM43  4.7U_0603_6.3V6K  [C_0603]  112.68 148.32 0 top
CM46  0.1U_0402_10V7K  [C_0402]  117 147.7 90 top
CM47  0.1U_0402_10V7K  [C_0402]  105.69 147.76 90 top
CM48  0.1U_0402_10V7K  [C_0402]  111.73 147.48 90 top
CR1  0.1U_0402_10V7K  [C_0402]  177.98 18.06 270 top
CR2  4.7U_0603_6.3V6K  [C_0603]  179.06 17.98 270 top
CR3  1U_0402_6.3V6K  [C_0402]  180.14 17.14 90 top
CR4  1U_0402_6.3V6K  [C_0402]  172.42 22.17 0 top
CR5  5P_0402_50V8C  [C_0402]  181.79 21.83 180 top
CR6  5P_0402_50V8C  [C_0402]  177.32 28.03 270 top
CR7  0.1U_0402_10V7K  [C_0402]  186.46 31.62 90 top
CR8  4.7U_0603_6.3V6K  [C_0603]  185.32 31.38 90 top
CR9  22P_0402_50V8J  [C_0402]  179.58 27.13 90 top
CR10  22P_0402_50V8J  [C_0402]  181.77 23.61 270 top
CR11  22P_0402_50V8J  [C_0402]  175.16 26.99 90 top
CS5  1000P_0402_50V7K  [C_0402]  221.64 56.41 270 bottom
CS6  0.1U_0402_25V6K  [C_0402]  221.64 60.32 90 bottom
CS7  10U_0805_10V6K  [C_0805]  220.12 60.18 90 bottom
CS8  0.01U_0402_16V7K  [C_0402]  222.36 99.62 180 bottom
CS9  0.01U_0402_16V7K  [C_0402]  222.36 100.63 180 bottom
CS10  1000P_0402_50V7K  [C_0402]  221.39 113.92 90 bottom
CS11  0.1U_0402_25V6K  [C_0402]  222.41 113.92 90 bottom
CS12  10U_0805_10V6K  [C_0805]  219.87 113.78 90 bottom
CS13  1U_0402_6.3V6K  [C_0402]  216.51 107.26 180 top
CS14  0.01U_0402_16V7K  [C_0402]  222.36 103.43 180 bottom
CS15  0.01U_0402_16V7K  [C_0402]  222.36 104.44 180 bottom
CS16  0.1U_0603_25V7K  [C_0603]  222.34 110.06 180 bottom
CS17  0.1U_0402_25V6K  [C_0402]  222.36 116.15 180 bottom
CS105  0.01U_0402_16V7K  [C_0402]  221.59 38.79 180 bottom
CS106  0.01U_0402_16V7K  [C_0402]  221.59 39.81 180 bottom
CS108  0.01U_0402_16V7K  [C_0402]  221.59 43.62 180 bottom
CS109  0.01U_0402_16V7K  [C_0402]  221.59 42.6 180 bottom
CT1  10U_0603_6.3V6M  [C_0603]  204.31 153.87 180 bottom
CT2  0.1U_0402_16V7K  [C_0402]  206.02 160.65 90 top
CT3  0.1U_0402_16V7K  [C_0402]  204.07 155.01 180 bottom
CT4  10U_0603_6.3V6M  [C_0603]  199.36 166.44 180 bottom
CT5  0.1U_0402_16V7K  [C_0402]  199.11 165.3 180 bottom
CT6  22U_0805_6.3V6M  [C_0805]  200.31 167.88 90 bottom
CT7  0.1U_0402_16V7K  [C_0402]  202.97 168.65 90 bottom
CT8  0.1U_0402_16V7K  [C_0402]  199.11 164.41 180 bottom
CT9  10U_0603_6.3V6M  [C_0603]  196.09 159.24 270 bottom
CT10  0.1U_0402_16V7K  [C_0402]  197.67 159.27 270 bottom
CT11  0.1U_0402_16V7K  [C_0402]  208.13 164.03 180 top
CT12  0.1U_0402_16V7K  [C_0402]  203.48 158.39 270 bottom
CX1  0.1U_0402_10V7K  [C_0402]  216.87 174.45 0 top
CX2  0.1U_0402_10V7K  [C_0402]  213.08 165.56 180 bottom
CX3  10U_0805_10V6K  [C_0805]  213.72 164.5 270 bottom
CX4  2.2U_0402_25V7K  [C_0402]  217.33 176.53 90 top
CX5  0.1U_0603_25V7K  [C_0603]  223.23 177.11 0 top
CX6  0.1U_0402_16V7K  [C_0402]  23.52 94.77 270 bottom
CX7  4.7U_0805_10V4Z  [C_0805]  213.9 158.61 90 bottom
CX8  4.7U_0805_10V4Z  [C_0805]  216.02 169.87 180 bottom
CX9  0.1U_0402_10V7K  [C_0402]  217.07 160.17 270 bottom
CX10  0.1U_0402_10V7K  [C_0402]  193.65 168.48 180 bottom
CX11  0.1U_0402_10V7K  [C_0402]  215.24 171.27 180 bottom
CX12  0.1U_0402_10V7K  [C_0402]  19.76 101.67 0 bottom
CX13  0.1U_0402_10V7K  [C_0402]  19.76 100.66 0 bottom
CX14  0.1U_0402_10V7K  [C_0402]  18.75 104.47 0 bottom
CX15  0.1U_0402_10V7K  [C_0402]  18.75 103.45 0 bottom
CX16  0.1U_0402_10V7K  [C_0402]  18.49 98.88 0 bottom
CX17  0.1U_0402_10V7K  [C_0402]  18.49 97.86 0 bottom
CX18  0.1U_0402_10V7K  [C_0402]  19.51 95.83 0 bottom
CX19  0.1U_0402_10V7K  [C_0402]  19.51 94.82 0 bottom
CX20  4.7U_0805_10V4Z  [C_0805]  212.63 168.26 90 bottom
CX21  0.1U_0402_16V7K  [C_0402]  14.13 107.47 270 bottom
CX22  10U_0603_6.3V6M  [C_0603]  15.4 107.45 270 bottom
CX23  3.3P_0402_50V8C  [C_0402]  15.14 101.72 90 bottom
CX24  3.3P_0402_50V8C  [C_0402]  15.14 100.61 270 bottom
CX25  3.3P_0402_50V8C  [C_0402]  14.13 104.33 90 bottom
CX26  3.3P_0402_50V8C  [C_0402]  14.13 103.46 270 bottom
CX27  3.3P_0402_50V8C  [C_0402]  13.36 98.93 90 bottom
CX28  3.3P_0402_50V8C  [C_0402]  13.36 97.81 270 bottom
CX29  3.3P_0402_50V8C  [C_0402]  14.89 95.88 90 bottom
CX30  3.3P_0402_50V8C  [C_0402]  14.89 94.77 270 bottom
CX42  0.1U_0402_10V7K  [C_0402]  205.26 157.48 90 bottom
CX43  0.1U_0402_10V7K  [C_0402]  206.28 157.48 90 bottom
CX44  0.1U_0402_10V7K  [C_0402]  207.29 157.48 90 bottom
CX46  0.1U_0402_10V7K  [C_0402]  204.37 157.48 90 bottom
CX50  10U_0603_6.3V6M  [C_0603]  201.83 168.16 90 bottom
CX51  4.7U_0805_10V4Z  [C_0805]  33.94 78.27 270 bottom
DA8  -  [BAT54C-7-F_SOT23-3]  192.18 44.17 180 top
DA10  AZ5125-02S.R7G_SOT23-3  [AZ5125-02SPR7G_SOT23-3]  21.36 22.58 0 bottom
DA12  AZ5125-02S.R7G_SOT23-3  [AZ5125-02SPR7G_SOT23-3]  17.3 22.58 0 bottom
DC1  -  [RB751V40_SC76-2]  96.85 108.66 0 top
DC3  -  [BAV70W-7-F_SOT323-3]  181.26 108.09 0 bottom
DE1  -  [L03ESDL5V0CG3-2_SOT-523-3]  174.72 54.68 90 top
DE3  PESD5V0U2BT_SOT23-3~D  [PESD5V0U2BT_SOT23-3]  67.59 114.09 0 top
DI1  IP4292CZ10-TBR_XSON10_2.5X1~D  [IP4292CZ10-TBR_XSON10_2P5X1]  16.37 61.05 90 bottom
DI2  -  [L30ESDL5V0C3-2_SOT23-3]  16.89 57.99 90 bottom
DI8  -  [L30ESDL5V0C3-2_SOT23-3]  14.35 28.27 90 bottom
DI9  -  [L30ESDL5V0C3-2_SOT23-3]  16.89 46.05 90 bottom
DX1  -  [RB751V-40_SOD323-2]  221.52 162.05 270 bottom
FD1  FIDUCAL  [FIDUCIAL_C40M80]  32.29 13.66 0 top
FD2  FIDUCIAL  [FIDUCIAL_C40M80]  32.29 13.66 180 bottom
FD3  FIDUCAL  [FIDUCIAL_C40M80]  194.21 182.7 180 bottom
FD4  FIDUCIAL  [FIDUCIAL_C40M80]  194.21 182.7 0 top
FD5  FIDUCIAL  [FIDUCIAL_C40M80]  202.8 24.19 0 top
FD6  FIDUCAL  [FIDUCIAL_C40M80]  87.83 149.95 180 bottom
FD7  FIDUCAL  [FIDUCIAL_C40M80]  202.81 24.19 180 bottom
FD8  FIDUCIAL  [FIDUCIAL_C40M80]  87.82 149.95 0 top
FX1  1.5A_6V_1206L150PR~D  [F_1206L150PR]  14.25 109.04 0 bottom
H2  -  [H_2P8]  109.2 13.4 0 top
H4  -  [H_2P8]  225.2 4.9 0 top
H5  -  [H_2P8]  225.2 168.4 0 top
H6  -  [H_3P3]  26.92 119.1 0 top
H7  -  [H_3P3]  19.2 38.1 0 top
H8  -  [H_2P8]  164.2 185.4 0 top
H9  -  [H_2P8]  127.6 154.8 0 top
H10  -  [H_3P3]  153.3 144.5 0 top
H11  -  [H_2P8]  225.2 81.4 0 top
H12  -  [H_2P8]  31.2 109.4 0 top
H16  -  [H_2P8]  21.9 4.9 0 top
H17  -  [H_2P8]  19.2 71.9 0 top
H18  -  [H_3P3]  204.1 94.4 0 top
H31  -  [H_3P7]  80.8 129.05 0 top
H32  -  [H_3P7]  141.2 103.66 0 top
H33  -  [H_3P7]  80.8 103.66 0 top
H34  -  [H_3P7]  141.2 129.05 0 top
H35  -  [H_3P7X3P2N]  195.55 187.5 0 top
JBATT1  LOTES_AAA-BAT-054-K01  [LOTES_AAA-BAT-054-K01_2P]  188.2 109.4 270 bottom
JDB1  MOLEX_52435-2671_26P_P0.5  [MOLEX_52435-2671_26P-T]  55.88 74.95 0 top
JDIMM1  FOX_AS0A626-U8SN-7F  [LCN_DAN06-K4406-0102_204P]  82.75 69.44 0 bottom
JFAN  ACES_85204-0300N  [ACES_85204-0300N_3P]  48.7 108.6 0 bottom
JHDD  SANTA_193202-1  [SANTA_193202-1_22P]  227.22 37.39 270 bottom
JHDMI  LOTES_ABA-HDM-022-K01  [LOTES_ABA-HDM-022-K01_19P]  8.08 99.15 270 bottom
JHP  SINGA_2SJ-E960-001F  [SINGA_2SJ-E960-001F_6P]  11.1 7 90 bottom
JKB  HB_A823020-SBHR21  [HB_A823020-SBHR21_30P]  228.72 159.85 270 top
JLAN  SANTA_130456-311  [SANTA_130456-311_8P]  15 79.23 90 bottom
JLVDS  STARC_107K40-000001-G2  [STARC_107K40-000001-G2_40P]  204.45 173.45 0 bottom
JMINI  CONCR_525B01BE17A  [CONCR_525B01BE17A_52P]  93.3 150.67 0 bottom
JODD  SANTA_202801-1  [SANTA_202801-1_13P]  227.05 98.22 270 bottom
JP3  2MM  [JUMP_43X39]  45.75 74.93 90 bottom
JP4  2MM  [JUMP_43X39]  45.75 80.8 270 bottom
JP5  2MM  [JUMP_43X39]  45.75 77.47 90 bottom
JP6  2MM  [JUMP_43X39]  46.08 82.75 180 bottom
JP7  -  [JUMP_43X79]  216.82 109 90 top
JP8  2MM  [JUMP_43X39]  14.13 54.23 90 bottom
JP12  -  [JUMP_43X39]  181.13 112.42 270 bottom
JP13  -  [JUMP_43X79]  219.65 57.48 180 bottom
JP14  JUMP  [JUMP_43X118]  123.73 93.33 270 top
JP15  JUMP  [JUMP_43X118]  109.25 93.33 270 top
JP36  JUMP  [JUMP_43X118]  97.73 29.82 180 bottom
JP37  JUMP  [JUMP_43X118]  109.59 25.22 0 bottom
JP38  JUMP  [JUMP_43X79]  54.3 99.9 180 top
JP39  JUMP  [JUMP_43X79]  55.4 106.2 90 top
JPWR  HB_A090420-SAHR21  [HB_A090420-SAHR21_4P]  45.35 95.5 180 top
JREAD  T-SOL_143-2300302602_RV  [T-SOL_143-2300302602_22P_RV]  191.48 29.93 180 bottom
JSPK  E&T_3703-Q04N-11R  [E-T_3703-Q04N-11R_4P]  69.62 21.9 90 top
JTOUCH  ACES_88460-00601-P01  [ACES_88460-00601-P01_6P]  23.71 96.9 180 top
JTP  PS_HPF10052-06M000R  [PS_HPF10052-06M000R_6P]  66.35 110.35 0 top
JUSB1  ACON_UARBG-4K1926  [ACON_UARBG-4K1926_4P]  10.32 67.1 90 bottom
JUSB7  ACON_UARBG-4K1926  [ACON_UARBG-4K1926_4P]  10.32 31.9 90 bottom
JUSB8  ACON_UARBG-4K1926  [ACON_UARBG-4K1926_4P]  10.32 49.5 90 bottom
L1  BLM15AG601SN1D_2P  [MURAT_BLM15AG601SN1D_2P]  104.98 135.12 225 bottom
LA1  BLM15BB221SN1D_2P  [MURAT_BLM15BB221SN1D_2P]  45.56 26.9 90 top
LA3  0_0603_5%  [R_0603]  64.04 20.2 0 top
LA4  0_0603_5%  [R_0603]  64.04 21.92 0 top
LA5  0_0603_5%  [R_0603]  63.08 23.7 0 top
LA6  0_0603_5%  [R_0603]  63.08 25.41 0 top
LA7  NBQ100505T-800Y-N_2P  [CHILI_NBQ100505T-800Y-N_2P]  16.27 17.05 270 bottom
LA8  NBQ100505T-800Y-N_2P  [CHILI_NBQ100505T-800Y-N_2P]  21.12 15.82 0 bottom
LA9  NBQ100505T-800Y-N_2P  [CHILI_NBQ100505T-800Y-N_2P]  21.12 17.35 0 bottom
LA10  NBQ100505T-800Y-N_2P  [CHILI_NBQ100505T-800Y-N_2P]  18.05 17.05 270 bottom
LE1  FBMA-L11-160808-800LMT_0603  [KC_FBMA-L11-160808-800LMT_2P]  199.68 50.87 0 top
LE2  FBMA-L11-160808-800LMT_0603  [KC_FBMA-L11-160808-800LMT_2P]  195.99 71.18 270 top
LED1  HT-210UD5-BP5_AMBER-WHITE  [LED_HT-210UD5-BP5_3P]  28.9 10.7 0 top
LED2  WHITE  [LED_12-21C-T3D-CM2P1B18X-2C_3P]  40.8 10.74 0 top
LED4  WHITE  [LED_12-21C-T3D-CM2P1B18X-2C_3P]  58.81 10.7 0 top
LI1  DLW21SN670HQ2L_4P  [MURAT_DLW21SN670HQ2L_4P]  21.07 60.63 180 bottom
LI2  WCM-2012HS-900T_4P  [KC_WCM-2012HS-900T_4P]  23.1 58.39 180 bottom
LI3  DLW21SN670HQ2L_4P  [MURAT_DLW21SN670HQ2L_4P]  21.07 62.41 180 bottom
LI5  WCM-2012HS-900T_4P  [KC_WCM-2012HS-900T_4P]  23.1 46.45 180 bottom
LI6  WCM-2012HS-900T_4P  [KC_WCM-2012HS-900T_4P]  20.06 28.67 180 bottom
LR2  WCM-2012HS-900T_4P  [KC_WCM-2012HS-900T_4P]  166.14 33.22 270 bottom
LT1  FBMA-L11-201209-221LMA30T_0805  [KC_FBMA-L11-201209-221LMA30_2P]  198.72 168.1 180 bottom
LT2  FBMA-L11-201209-221LMA30T_0805  [KC_FBMA-L11-201209-221LMA30_2P]  205.58 153.87 0 bottom
LT3  4.7UH_PG031B-4R7MS_1.1A_20%  [CYNTE_PG031B-4R7MS_2P]  197.32 160.71 90 bottom
LX1  FBMA-L11-201209-221LMA30T_0805  [KC_FBMA-L11-201209-221LMA30_2P]  214.34 166.32 0 bottom
LX2  WCM-2012HS-900T_4P  [KC_WCM-2012HS-900T_4P]  18.02 101.57 180 bottom
LX3  WCM-2012HS-900T_4P  [KC_WCM-2012HS-900T_4P]  17.01 104.36 180 bottom
LX4  WCM-2012HS-900T_4P  [KC_WCM-2012HS-900T_4P]  16.25 98.77 180 bottom
LX5  WCM-2012HS-900T_4P  [KC_WCM-2012HS-900T_4P]  17.77 95.72 180 bottom
LX6  WCM-2012HS-900T_4P  [KC_WCM-2012HS-900T_4P]  218.67 166.71 90 bottom
NOREF  -  []  82.07 -31.53 0 top
NOREF#2  -  []  204.1 94.4 0 top
NOREF#3  -  []  74.7 46.96 0 top
NOREF#4  -  []  109.2 13.4 0 top
NOREF#5  -  []  225.2 81.4 0 top
NOREF#6  -  []  139.22 48.02 0 top
NOREF#7  -  []  127.6 154.8 0 top
NOREF#8  -  []  141.2 103.65 0 top
NOREF#9  -  []  19.2 71.9 0 top
NOREF#10  -  []  164.2 185.4 0 top
NOREF#11  -  []  79.78 43.08 0 top
NOREF#12  -  []  26.92 119.1 0 top
NOREF#13  -  []  225.2 4.9 0 top
NOREF#14  -  []  79.66 15.95 0 top
NOREF#15  -  []  31.2 109.4 0 top
NOREF#16  -  []  153.3 144.5 0 top
NOREF#17  -  []  80.8 129.06 0 top
NOREF#18  -  []  19.2 38.1 0 top
NOREF#19  -  []  130.65 220.1 0 top
NOREF#20  -  []  225.2 168.4 0 top
NOREF#21  -  []  80.8 103.66 0 top
NOREF#22  -  []  141.2 129.05 0 top
NOREF#23  -  []  21.9 4.9 0 top
NOREF#24  -  []  100.93 50.24 0 top
NOREF#25  -  []  93.84 40.4 180 bottom
NOREF#26  -  []  170.46 77.48 180 bottom
NOREF#27  -  []  147.29 89.36 180 bottom
NOREF#28  -  []  171.99 83.28 180 bottom
PBATT1  SUYIN_200028MR009G502ZL  [SUYIN_200028MR009G502ZL_9P]  139.52 188.7 0 bottom
PC1  1000P_0402_50V7K  [C_0402]  139.04 171.39 0 top
PC2  100P_0402_50V8J  [C_0402]  139.04 170.42 0 top
PC3  1000P_0402_50V7K  [C_0402]  130.35 165.03 270 top
PC4  100P_0402_50V8J  [C_0402]  129.41 165.03 270 top
PC5  0.01U_0402_25V7K  [C_0402]  155.48 182.37 90 top
PC6  1000P_0402_50V7K  [C_0402]  155.48 185.06 270 top
PC7  1000P_0402_50V7K  [C_0402]  199.34 73.73 0 top
PC8  0.1U_0402_25V6  [C_0402]  130.26 172.07 90 top
PC9  0.01U_0402_25V7K  [C_0402]  128.94 181.44 90 top
PC11  .1U_0402_16V7K  [C_0402]  129.64 186.01 270 top
PC102  220U_6.3V_M  [C_6R3AVEA221M0645]  138.82 18.08 0 bottom
PC103  220U_6.3V_M  [C_6R3AVEA221M0645]  118.82 18.26 180 bottom
PC105  1U_0603_10V6K  [C_0603]  129.21 12.88 270 top
PC106  100P_0402_50V8J  [C_0402]  130.36 12.04 90 bottom
PC107  100P_0402_50V8J  [C_0402]  128.07 12.95 270 bottom
PC108  10U 25V K X5R 0805  [C_0805]  129.77 26.83 270 top
PC109  0.1U_0402_25V6  [C_0402]  126.52 25.04 270 bottom
PC110  2200P_0402_50V7K  [C_0402]  131.47 25.04 270 bottom
PC111  10U 25V K X5R 0805  [C_0805]  127.77 26.82 270 top
PC112  0.1U_0603_25V7K  [C_0603]  133.06 15.82 0 top
PC113  0.1U_0603_25V7K  [C_0603]  124.04 15.82 0 top
PC114  680P_0603_50V8J  [C_0603]  133.82 21.28 180 top
PC115  680P_0603_50V8J  [C_0603]  122.77 21.66 0 top
PC116  1U_0603_25V6K  [C_0603]  129.89 17.73 180 bottom
PC117  1U_0603_10V6K  [C_0603]  129.1 20.09 180 bottom
PC118  4.7U_0805_25V6-K  [C_0805]  123.89 12.57 0 bottom
PC201  330U_2.5V_M  [C_MP6VU330MC6]  144.6 23.57 0 bottom
PC203  0.1U_0402_25V6  [C_0402]  161.83 17.6 270 bottom
PC204  2200P_0402_50V7K  [C_0402]  158.21 19.42 90 bottom
PC205  10U 25V K X5R 0805  [C_0805]  158.65 17.55 270 bottom
PC206  10U 25V K X5R 0805  [C_0805]  160.49 17.55 270 bottom
PC207  0.1U_0603_25V7K  [C_0603]  153.7 22.92 0 bottom
PC208  10U_0805_6.3V6K  [C_0805]  153.7 28.38 270 bottom
PC209  10U_0805_6.3V6K  [C_0805]  155.67 29.84 0 bottom
PC210  1U_0603_10V6K  [C_0603]  158.46 21.27 90 bottom
PC211  680P_0402_50V7K  [C_0402]  156.42 12.39 0 bottom
PC212  0.033U_0402_16V7K  [C_0402]  158.46 29.46 90 bottom
PC213  1U_0603_10V6K  [C_0603]  159.67 22.67 270 bottom
PC214  0.1U_0402_10V7K  [C_0402]  160.87 25.52 0 bottom
PC215  0.1U_0402_10V7K  [C_0402]  160.87 27.43 0 bottom
PC300  22U_0603_6.3V6M  [C_0603]  168.98 114.25 0 bottom
PC301  68P_0402_50V8J  [C_0402]  172.7 109.68 180 bottom
PC302  22U_0603_6.3V6M  [C_0603]  164.68 108.66 0 bottom
PC303  22U_0603_6.3V6M  [C_0603]  164.68 110.56 0 bottom
PC304  .1U_0402_16V7K  [C_0402]  167.77 109.37 270 bottom
PC305  680P_0402_50V7K  [C_0402]  168.81 116.48 270 bottom
PC306  680P_0402_50V7K  [C_0402]  50.19 95.4 270 bottom
PC307  22U_0603_6.3V6M  [C_0603]  53.11 91.32 270 bottom
PC308  22U_0603_6.3V6M  [C_0603]  56.86 94.94 0 bottom
PC309  .1U_0402_16V7K  [C_0402]  48.49 92.78 180 bottom
PC310  68P_0402_50V8J  [C_0402]  51.34 88.14 90 bottom
PC311  22U_0603_6.3V6M  [C_0603]  56.86 96.21 0 bottom
PC400  22U_0603_6.3V6M  [C_0603]  63.4 87.13 180 bottom
PC401  68P_0402_50V8J  [C_0402]  59.71 91.59 0 bottom
PC402  22U_0603_6.3V6M  [C_0603]  67.41 91.02 180 bottom
PC403  22U_0603_6.3V6M  [C_0603]  67.43 92.9 180 bottom
PC404  .1U_0402_16V7K  [C_0402]  64.52 91.9 90 bottom
PC405  680P_0402_50V7K  [C_0402]  63.4 84.71 90 bottom
PC411  1U_0402_6.3V6K  [C_0402]  169.02 153.74 180 bottom
PC412  4.7U_0603_6.3V6K  [C_0603]  166.96 152.6 90 bottom
PC413  0.01U_0402_25V7K  [C_0402]  171.85 144.4 90 bottom
PC414  22U_0603_6.3V6M  [C_0603]  168.18 144.89 0 bottom
PC415  .1U_0402_16V7K  [C_0402]  171.5 153.69 90 bottom
PC501  100U_25V_M  [C_ECST250ADA101MF611]  137.19 142.98 90 bottom
PC502  1000P_0402_50V7K  [C_0402]  166.06 139.05 0 bottom
PC503  0.01UF_0402_25V7K  [C_0402]  163.41 133.91 90 top
PC504  120P_0402_50V8J  [C_0402]  164.35 137.24 0 bottom
PC505  470P_0402_50V7K  [C_0402]  167.27 137.23 0 bottom
PC506  6800P_0402_25V7K  [C_0402]  161.65 139.9 180 top
PC507  1000P_0402_50V8-J  [C_0402]  164.35 138.11 0 bottom
PC508  2200P_0402_50V7K  [C_0402]  142.07 145.62 0 bottom
PC509  10U 25V K X5R 0805  [C_0805]  141.67 144.09 0 top
PC510  10U 25V K X5R 0805  [C_0805]  141.67 144.09 0 bottom
PC511  820PF_0402_50V7K  [C_0402]  163.41 139.03 180 bottom
PC512  .1U_0402_16V7K  [C_0402]  164.44 139.27 180 top
PC513  0.1U_0603_25V7K  [C_0603]  163.63 138.3 270 top
PC514  0.033U 25V K X7R 0402  [C_0402]  162.59 138.2 270 top
PC515  0.1U_0603_25V7K  [C_0603]  158.92 136.9 270 bottom
PC516  680P_0402_50V7K  [C_0402]  137.11 138.25 0 top
PC517  1U_0603_10V6K  [C_0603]  162.02 133.3 180 top
PC518  1U_0603_10V6K  [C_0603]  160.62 132.03 0 top
PC519  10U 25V K X5R 0805  [C_0805]  151.48 127.1 180 bottom
PC520  47P_0402_50V8J  [C_0402]  167.01 131.99 0 bottom
PC521  0.1U_0402_25V6  [C_0402]  151.08 128.5 180 bottom
PC522  10U 25V K X5R 0805  [C_0805]  151.37 127.33 180 top
PC523  0.1U_0402_16V7K  [C_0402]  167.92 132.01 270 top
PC524  0.1U_0603_25V7K  [C_0603]  159.44 128.92 90 bottom
PC525  820PF_0402_50V7K  [C_0402]  162.57 126.65 0 bottom
PC526  680P_0402_50V7K  [C_0402]  151.59 121.38 180 top
PC527  470P_0402_50V7K  [C_0402]  168.05 127.38 90 bottom
PC528  180P_0402_50V8J  [C_0402]  165.26 128.45 180 bottom
PC529  0.033U 25V K X7R 0402  [C_0402]  162.46 127.15 270 top
PC530  0.1U_0603_25V7K  [C_0603]  163.61 127.9 270 top
PC531  1000P_0402_50V8-J  [C_0402]  163.47 127.52 90 bottom
PC532  6800P_0402_25V7K  [C_0402]  160.73 125.3 0 top
PC533  330P_0402_50V7K  [C_0402]  168.94 128.29 270 bottom
PC534  .1U_0402_16V7K  [C_0402]  162.97 125.25 270 top
PC535  0.01UF_0402_25V7K  [C_0402]  163.4 131.78 270 top
PC700  0.1U_0603_25V7K  [C_0603]  144.81 160.54 270 top
PC701  5600P_0402_25V7K  [C_0402]  143.28 157.76 270 top
PC702  4.7U_0805_25V6-K  [C_0805]  148.62 165.09 90 bottom
PC703  4.7U_0805_25V6-K  [C_0805]  146.84 165.09 90 bottom
PC704  2200P_0402_25V7K  [C_0402]  144.17 165.48 90 bottom
PC705  0.1U_0603_25V7K  [C_0603]  145.32 165.24 90 bottom
PC706  0.1U_0603_25V7K  [C_0603]  167.91 169.24 0 bottom
PC707  0.1U_0603_25V7K  [C_0603]  167.91 170.46 0 bottom
PC708  0.1U_0402_10V7K  [C_0402]  138.87 164.16 90 top
PC709  0.047U_0603_25V7M  [C_0603]  166.81 168.51 90 top
PC710  1U_0603_10V6K  [C_0603]  167.91 171.68 0 bottom
PC711  1U_0603_25V6K  [C_0603]  167.97 175.19 270 bottom
PC712  0.01U_0402_50V7K  [C_0402]  170.29 170.46 270 bottom
PC713  0.1U_0603_25V7K  [C_0603]  164.81 174.32 0 bottom
PC714  1U_0603_10V6K  [C_0603]  169.19 175.19 270 bottom
PC715  0.1U_0402_10V7K  [C_0402]  173.82 172.26 180 bottom
PC716  680P_0402_50V7K  [C_0402]  148.87 170.13 270 bottom
PC717  10U 25V K X5R 0805  [C_0805]  156.4 184.86 0 bottom
PC718  10U 25V K X5R 0805  [C_0805]  156.4 183.08 0 bottom
PC719  10U 25V K X5R 0805  [C_0805]  157.42 181.3 0 bottom
PC720  10U 25V K X5R 0805  [C_0805]  159.58 179.53 0 bottom
PC721  2200P_0402_25V7K  [C_0402]  172.09 169.54 90 bottom
PC722  0.22U_0603_25V7K  [C_0603]  171.54 177.37 0 top
PC723  0.1U_0402_10V7K  [C_0402]  175.16 167.79 270 top
PC725  0.1U_0402_16V7K  [C_0402]  175.09 169.19 0 top
PC726  0.1U_0603_25V7K  [C_0603]  173.96 177.37 0 top
PC727  0.01U_0402_25V7K  [C_0402]  174.2 165.94 0 top
PC901  22U_0603_6.3V6M  [C_0603]  149.36 99.98 90 bottom
PC902  22U_0805_6.3V6M  [C_0805]  116.53 82.37 0 top
PC903  22U_0603_6.3V6M  [C_0603]  150.63 99.98 90 bottom
PC904  22U_0805_6.3V6M  [C_0805]  116.53 85.42 0 top
PC905  22U_0603_6.3V6M  [C_0603]  151.9 99.98 90 bottom
PC906  22U_0805_6.3V6M  [C_0805]  113.15 85.42 180 top
PC907  22U_0603_6.3V6M  [C_0603]  153.17 99.98 90 bottom
PC908  22U_0805_6.3V6M  [C_0805]  108.32 85.42 180 top
PC909  220U_D2_2VY_R15M  [C_D2]  149.33 114.15 0 bottom
PC911  220U_D2_2VY_R15M  [C_D2]  149.33 109.32 0 bottom
PC913  22U_0603_6.3V6M  [C_0603]  132.24 136.66 90 bottom
PC914  22U_0603_6.3V6M  [C_0603]  126.14 136.79 90 bottom
PC915  22U_0603_6.3V6M  [C_0603]  132.17 135.46 180 bottom
PC916  22U_0603_6.3V6M  [C_0603]  132.17 134.19 180 bottom
PC917  220U_D2_2VY_R15M  [C_D2]  123.35 139.5 90 top
PC918  220U_D2_2VY_R15M  [C_D2]  122.84 141.02 90 bottom
PC919  220U_D2_2VY_R15M  [C_D2]  118.42 141.3 180 bottom
PC920  22U_0603_6.3V6M  [C_0603]  115.33 120.46 225 top
PC921  22U_0603_6.3V6M  [C_0603]  113.68 118.58 135 top
PC922  22U_0603_6.3V6M  [C_0603]  113.17 122.74 225 top
PC923  1U_0402_6.3V6K  [C_0402]  109.43 119.78 315 top
PC924  1U_0402_6.3V6K  [C_0402]  110.58 120.78 45 top
PC925  1U_0402_6.3V6K  [C_0402]  113.5 121.56 315 top
PC926  0.1U_0402_16V7K  [C_0402]  132.19 138.12 180 top
PC927  0.1U_0402_16V7K  [C_0402]  132.19 136.85 180 top
PC928  0.1U_0402_16V7K  [C_0402]  132.19 135.58 180 top
PC929  22U_0603_6.3V6M  [C_0603]  106.34 111.85 45 top
PC930  10U_0603_6.3V6M  [C_0603]  111.68 118.71 315 top
PC931  22U_0603_6.3V6M  [C_0603]  108.9 115.88 315 top
PC932  22U_0603_6.3V6M  [C_0603]  109.97 117.02 315 top
PC933  2.2U_0402_6.3V6M  [C_0402]  107.65 114.76 315 top
PC934  2.2U_0402_6.3V6M  [C_0402]  112.16 115 45 top
PD1  -  [TVNST52302AB0_SOT523-3]  143.77 183.67 0 bottom
PD2  -  [TVNST52302AB0_SOT523-3]  145.9 183.67 0 bottom
PH1  100K_0402_1%_NCP15WF104F03RC  [R_0402]  124.95 118.69 180 top
PH500  10K_0402_1%_ERTJ0EG103FA  [R_0402]  133.25 141.88 270 bottom
PH501  470K_0402_5%_TN05-4R474JR  [R_0402]  142.19 140.03 0 top
PH502  470K_0402_5%_TN05-4R474JR  [R_0402]  150.45 124.13 270 top
PH503  10K_0402_1%_ERTJ0EG103FA  [R_0402]  157.86 116.48 90 bottom
PJP1  PAD-OPEN 1x3m  [JUMP_43X118]  133.96 182.33 0 top
PJP100  -  [JUMP_43X118]  119.73 12.93 270 bottom
PJP101  -  [JUMP_43X118]  135.28 13.32 270 bottom
PJP200  -  [JUMP_43X118]  164.75 19.12 180 bottom
PJP201  -  [JUMP_43X118]  144.71 28.9 90 bottom
PJP202  -  [JUMP_43X39]  154.08 31.62 90 bottom
PJP300  -  [JUMP_43X39]  173.68 114.5 180 bottom
PJP301  -  [JUMP_43X39]  162.88 109.36 180 bottom
PJP302  -  [JUMP_43X39]  54.72 88.34 180 bottom
PJP303  -  [JUMP_43X79]  54.81 96.34 180 bottom
PJP400  -  [JUMP_43X39]  58.92 87.15 0 bottom
PJP401  -  [JUMP_43X39]  69.2 91.77 0 bottom
PJP404  -  [JUMP_43X39]  165.51 149.69 0 bottom
PJP405  -  [JUMP_43X39]  166.49 145.87 180 bottom
PJPDC1  ACES_50299-00501-003  [ACES_50299-00501-003_5P]  136.9 178.4 270 bottom
PL1  FBMJ4516HS720NT_2P  [TAIYO_FBMJ4516HS720NT_2P]  134.16 166.49 180 bottom
PL2  FBMJ4516HS720NT_2P  [TAIYO_FBMJ4516HS720NT_2P]  134.23 182.34 0 bottom
PL3  FCM1005KF-102T03 0402  [MURAT_BLM15BX102SN1D_2P]  141.57 179.78 0 top
PL4  FBMJ4516HS720NT_2P  [TAIYO_FBMJ4516HS720NT_2P]  153.83 180.98 90 top
PL100  4.7UH_5.5A_20%_7X7X3_M  [L_7X7X3_M_2P]  140.39 25.07 180 bottom
PL101  4.7UH_5.5A_20%_7X7X3_M  [L_7X7X3_M_2P]  122.82 25.3 180 bottom
PL102  1UH_6.6A_20%_5X5X3_M  [L_5X5X3_M_2P]  128.58 31.88 270 bottom
PL200  1UH_11A_20%_7X7X3_M  [L_7X7X3_M_2P]  145.21 15.96 0 bottom
PL300  1UH_1239AS-H-1R0M-P2_3A_20%  [TOKO_1239AS-H-1R0M-P2_2P]  165.39 114.5 180 bottom
PL301  1UH_1239AS-H-1R0M-P2_3A_20%  [TOKO_1239AS-H-1R0M-P2_2P]  53.26 93.04 0 bottom
PL400  1UH_1239AS-H-1R0M-P2_3A_20%  [TOKO_1239AS-H-1R0M-P2_2P]  67.06 88.09 0 bottom
PL500  0.22UH_PCME064T-R22MS_28A_20%  [PANAS_ETQP4LR15AFM_4P]  129.03 146.57 270 bottom
PL501  0.22UH_PCME064T-R22MS_28A_20%  [PANAS_ETQP4LR15AFM_4P]  157.34 120.5 180 bottom
PL502  HCB2012KF-121T50_0805  [TAI-T_HCB2012KF-121T50_2P]  144.43 149.95 90 bottom
PL700  10UH_3.5A_20%_7X7X3_M  [L_7X7X3_M_2P]  154.11 172.64 90 bottom
PL701  1UH_2.8A_30%_4X4X2_F  [L_4X4X2_F_2P]  152.17 155.4 90 bottom
PQ1  FDV301N_G 1N SOT23-3  [FDV301N_NL_SOT23-3]  144.06 178.33 180 top
PQ2  MMST3904-7-F_SOT323~D  [RHU002N06_SOT323-3]  140.69 175.09 0 top
PQ3  L2N7002DW1T1G_SC88-6  [2N7002DW-T-R7_SOT363-6]  131.64 173.34 270 top
PQ4  L2N7002DW1T1G_SC88-6  [2N7002DW-T-R7_SOT363-6]  130.05 181.96 0 top
PQ101  -  [MDV1528URH_PDFN33-8-5]  134.47 27.42 90 top
PQ102  -  [MDV1528URH_PDFN33-8-5]  123.39 29.24 270 top
PQ103  -  [MDV1527URH_POWERDFN33-8-5]  131.52 25.05 270 top
PQ104  -  [MDV1527URH_POWERDFN33-8-5]  125.71 23.23 90 top
PQ201  -  [MDV1528URH_PDFN33-8-5]  154.13 17.77 90 bottom
PQ203  -  [MDV1527URH_POWERDFN33-8-5]  157.08 15.91 270 bottom
PQ501  AON7934_DFN3X3A-8-10  [AON7934_DFN3X3A8-10]  140.56 142.43 180 top
PQ503  AON7934_DFN3X3A-8-10  [AON7934_DFN3X3A8-10]  153.71 125.69 180 top
PQ701  -  [MDS1525URH_SO8]  155.86 164.29 270 bottom
PQ703  -  [MDS1525URH_SO8]  150.65 165.94 90 bottom
PQ704  -  [AO4407AL_SO8]  139.01 163.52 270 bottom
PQ705  SI4483ADY_SO8  [SI4459ADY-T1-GE3_SO8]  141.2 162.51 0 bottom
PQ706  -  [AO4407AL_SO8]  162.46 172.24 180 bottom
PQ707  PDTA144EU PNP_SOT323  [DTA144EUA_SC70-3]  140.87 158.23 180 top
PQ708  DDTC115EUA-7-F_SOT323  [DTC115EUA_SC70-3]  138.62 157.55 90 top
PQ709  DMN66D0LDW-7 2N SOT363-6  [2N7002DW-T-R7_SOT363-6]  137.81 160.63 0 top
PQ710  DMN66D0LDW-7 2N SOT363-6  [2N7002DW-T-R7_SOT363-6]  140.26 165.32 270 top
PQ711  DDTC115EUA-7-F_SOT323  [DTC115EUA_SC70-3]  171.99 163.1 0 top
PQ712  DDTC115EUA-7-F_SOT323  [DTC115EUA_SC70-3]  141.13 160.82 0 top
PQ713  DMN66D0LDW-7 2N SOT363-6  [2N7002DW-T-R7_SOT363-6]  135.5 159.43 180 top
PR1  33_0402_5%  [R_0402]  146.54 176.24 90 top
PR2  100K_0402_1%  [R_0402]  141.53 177.87 90 top
PR3  10K_0402_1%  [R_0402]  142.68 174.5 180 top
PR4  2.2K_0402_5%  [R_0402]  146.54 178.07 90 top
PR5  15K_0402_1%  [R_0402]  139.7 177.87 0 top
PR6  100_0402_5%  [R_0402]  144.33 182.7 270 bottom
PR7  10K_0402_1%  [R_0402]  143.34 181.81 180 bottom
PR8  100_0402_5%  [R_0402]  146.49 182.73 270 bottom
PR9  100_0402_5%  [R_0402]  145.39 182.73 270 bottom
PR10  12.1K_0402_1%  [R_0402]  198.28 72.77 90 top
PR11  3.01K_0402_1%  [R_0402]  199.29 69.47 90 top
PR12  3.3K_1206_5%~D  [R_1206]  129.45 168.24 90 top
PR13  0_0402_5%  [R_0402]  197.26 73.68 270 top
PR14  1M_0402_1%  [R_0402]  134.85 173.38 270 top
PR15  0_0402_5%  [R_0402]  200.31 70.38 270 top
PR16  200K_0402_1%  [R_0402]  128.42 172.11 0 top
PR17  160K_0402_1%  [R_0402]  131.5 180.54 180 top
PR18  10K_0402_1%  [R_0402]  201.32 70.38 270 top
PR19  1M_0402_1%  [R_0402]  132.89 174.42 0 top
PR20  10K_0402_1%  [R_0402]  199.34 72.72 0 top
PR21  10K_0402_1%  [R_0402]  128.42 173.02 0 top
PR26  100K_0402_1%  [R_0402]  130.56 185.11 0 top
PR100  13.7K_0402_1%  [R_0402]  130.36 12.04 90 top
PR101  30.9K_0402_1%  [R_0402]  128.07 12.95 270 top
PR102  20K_0402_1%  [R_0402]  131.31 12.04 90 bottom
PR103  20K_0402_1%  [R_0402]  127.12 12.95 270 bottom
PR104  187K_0402_1%  [R_0402]  131.3 12.04 90 top
